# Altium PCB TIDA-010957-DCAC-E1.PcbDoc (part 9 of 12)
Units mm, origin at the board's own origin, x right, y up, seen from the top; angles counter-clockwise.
Board outline 300 x 300 mm, 4 copper layers (Top Layer, Layer 1, Layer 2, Bottom Layer), stack 1.787 mm thick; 1159 components, 619 nets, 3431 pads, 2942 vias.
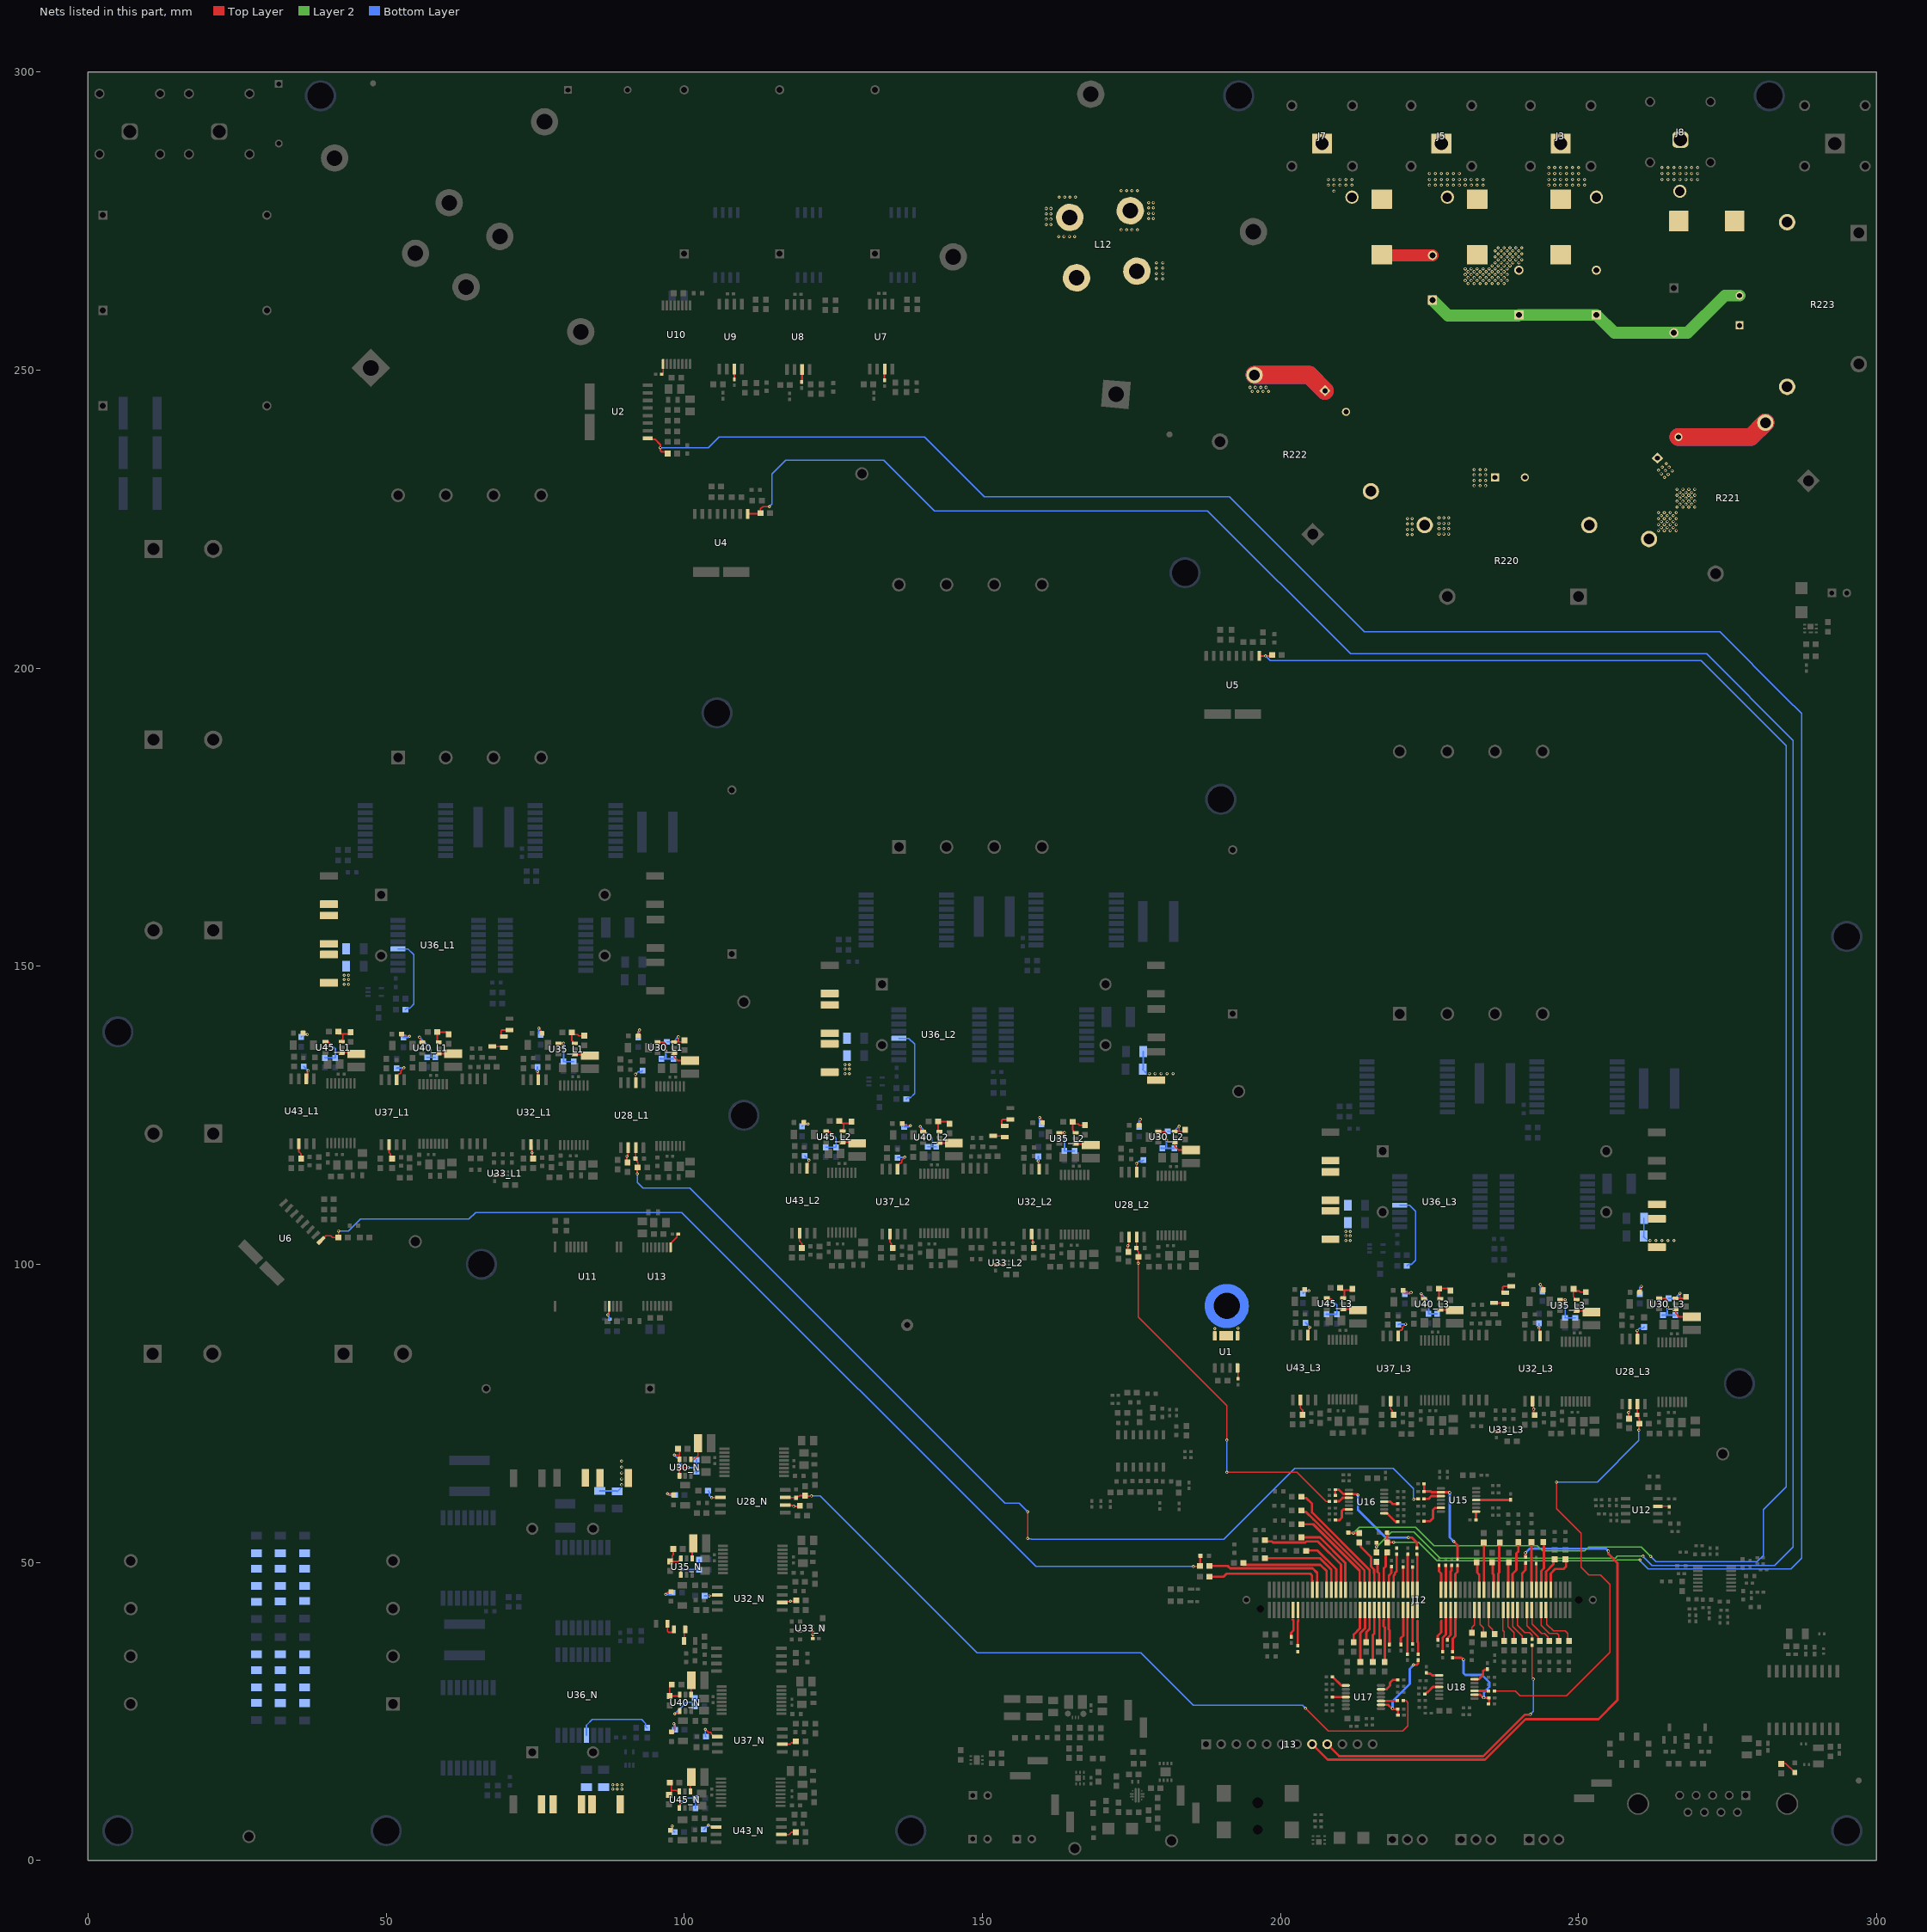
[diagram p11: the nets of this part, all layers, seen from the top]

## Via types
v1: diameter 0.508, hole 0.254, Top Layer to Bottom Layer, tented both sides, 2942 vias

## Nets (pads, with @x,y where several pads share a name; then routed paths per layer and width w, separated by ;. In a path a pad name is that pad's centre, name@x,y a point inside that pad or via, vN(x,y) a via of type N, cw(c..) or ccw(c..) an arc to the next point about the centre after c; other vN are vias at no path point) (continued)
NetD8_L2_2: D8_L2.2 R281_L2.2 R282_L2.2 | length 3.8
  Bottom Layer w0.254: R282_L2.2@176.97,135.686 176.97,132.803 R281_L2.2@176.917,132.75 176.917,132.661 R281_L2.2@177.44,132.138
  other v1: 178,132 179,132 180,132 181,132 182,132
NetD8_L3_1: D8_L3.1 D9_L3.2
NetD8_L3_2: D8_L3.2 R281_L3.2 R282_L3.2 | length 3.8
  Bottom Layer w0.254: R282_L3.2@260.97,107.686 260.97,104.803 R281_L3.2@260.917,104.75 260.917,104.661 R281_L3.2@261.44,104.138
  other v1: 262,104 263,104 264,104 265,104 266,104
NetD8_N_1: D8_N.1 D9_N.2
NetD8_N_2: D8_N.2 R281_N.2 R282_N.2 | length 3.8
  Bottom Layer w0.254: R282_N.2@85.814,61.97 88.697,61.97 R281_N.2@88.75,61.917 88.839,61.917 R281_N.2@89.362,62.44
  other v1: 89.5,63 89.5,64 89.5,65 89.5,66 89.5,67
NetD10_L1_2: D10_L1.2 R285_L1.1 | length 2.5
  Top Layer w0.3: D10_L1.2@92.3,138.2 92.462,138.362 92.462,139.262 v1(92.5,139.3)
  Bottom Layer w0.3: R285_L1.1@92.275,138.04 92.275,139.021 92.5,139.246 v1(92.5,139.3)
NetD10_L2_2: D10_L2.2 R285_L2.1 | length 2.5
  Top Layer w0.3: D10_L2.2@176.3,123.2 176.462,123.362 176.462,124.262 v1(176.5,124.3)
  Bottom Layer w0.3: R285_L2.1@176.275,123.04 176.275,124.021 176.5,124.246 v1(176.5,124.3)
NetD10_L3_2: D10_L3.2 R285_L3.1 | length 2.5
  Top Layer w0.3: D10_L3.2@260.3,95.2 260.462,95.362 260.462,96.262 v1(260.5,96.3)
  Bottom Layer w0.3: R285_L3.1@260.275,95.04 260.275,96.021 260.5,96.246 v1(260.5,96.3)
NetD10_N_2: D10_N.2 R285_N.1 | length 2.5
  Top Layer w0.3: v1(97.2,61.5) 97.238,61.462 98.138,61.462 D10_N.2@98.3,61.3
  Bottom Layer w0.3: v1(97.2,61.5) 97.254,61.5 97.479,61.275 R285_N.1@98.46,61.275
NetD11_L1_2: D11_L1.2 R296_L1.1 | length 2.6
  Top Layer w0.254: v1(75.613,139.6) 76,139.213 D11_L1.2@76,138.457
  Bottom Layer w0.254: v1(75.613,139.6) 75.613,138.774 R296_L1.1@75.93,138.457
NetD11_L2_2: D11_L2.2 R296_L2.1 | length 2.6
  Top Layer w0.254: v1(159.613,124.6) 160,124.213 D11_L2.2@160,123.457
  Bottom Layer w0.254: v1(159.613,124.6) 159.613,123.774 R296_L2.1@159.93,123.457
NetD11_L3_2: D11_L3.2 R296_L3.1 | length 2.6
  Top Layer w0.254: v1(243.613,96.6) 244,96.213 D11_L3.2@244,95.457
  Bottom Layer w0.254: v1(243.613,96.6) 243.613,95.774 R296_L3.1@243.93,95.457
NetD11_N_2: D11_N.2 R296_N.1 | length 2.6
  Top Layer w0.254: v1(96.9,44.613) 97.287,45 D11_N.2@98.043,45
  Bottom Layer w0.254: v1(96.9,44.613) 97.726,44.613 R296_N.1@98.043,44.93
NetD12_L1_2: D12_L1.2 R306_L1.1 | length 2.5
  Top Layer w0.254: D12_L1.2@52.589,138.224 52.599,138.234 53.919,138.234 v1(53.929,138.244)
  Bottom Layer w0.254: R306_L1.1@52.897,138.033 53.663,138.033 53.875,138.244 v1(53.929,138.244)
NetD12_L2_2: D12_L2.2 R306_L2.1 | length 2.5
  Top Layer w0.254: D12_L2.2@136.589,123.224 136.599,123.234 137.919,123.234 v1(137.929,123.244)
  Bottom Layer w0.254: R306_L2.1@136.897,123.033 137.663,123.033 137.875,123.244 v1(137.929,123.244)
NetD12_L3_2: D12_L3.2 R306_L3.1 | length 2.5
  Top Layer w0.254: D12_L3.2@220.589,95.224 220.599,95.234 221.919,95.234 v1(221.929,95.244)
  Bottom Layer w0.254: R306_L3.1@220.897,95.033 221.663,95.033 221.875,95.244 v1(221.929,95.244)
NetD12_N_2: D12_N.2 R306_N.1 | length 2.5
  Top Layer w0.254: v1(98.256,22.929) 98.266,22.919 98.266,21.599 D12_N.2@98.276,21.589
  Bottom Layer w0.254: v1(98.256,22.929) 98.256,22.875 98.467,22.663 R306_N.1@98.467,21.897
NetD13_L1_1: D13_L1.1 R319_L1.1 R320_L1.1
  other v1: 42.956,146.975 43.706,146.975 42.956,147.75 43.706,147.75 42.956,148.5 43.706,148.5
NetD13_L1_2: D13_L1.2 D15_L1.1
NetD13_L2_1: D13_L2.1 R319_L2.1 R320_L2.1
  other v1: 126.956,131.975 127.706,131.975 126.956,132.75 127.706,132.75 126.956,133.5 127.706,133.5
NetD13_L2_2: D13_L2.2 D15_L2.1
NetD13_L3_1: D13_L3.1 R319_L3.1 R320_L3.1
  other v1: 210.956,103.975 211.706,103.975 210.956,104.75 211.706,104.75 210.956,105.5 211.706,105.5
NetD13_L3_2: D13_L3.2 D15_L3.1
NetD13_N_1: D13_N.1 R319_N.1 R320_N.1
  other v1: 88,11.956 88.75,11.956 89.525,11.956 88,12.706 88.75,12.706 89.525,12.706
NetD13_N_2: D13_N.2 D15_N.1
NetD14_L1_1: D14_L1.1 D15_L1.2
NetD14_L2_1: D14_L2.1 D15_L2.2
NetD14_L3_1: D14_L3.1 D15_L3.2
NetD14_N_1: D14_N.1 D15_N.2
NetD16_L1_2: D16_L1.2 R323_L1.1 | length 1.9
  Top Layer w0.254: D16_L1.2@36.075,138.584 36.101,138.558 36.761,138.558 v1(36.786,138.532)
  Bottom Layer w0.254: R323_L1.1@35.768,138.109 35.768,138.134 36.116,138.482 36.668,138.482 36.718,138.532 v1(36.786,138.532)
NetD16_L2_2: D16_L2.2 R323_L2.1 | length 1.9
  Top Layer w0.254: D16_L2.2@120.075,123.584 120.101,123.558 120.761,123.558 v1(120.786,123.532)
  Bottom Layer w0.254: R323_L2.1@119.768,123.109 119.768,123.134 120.116,123.482 120.668,123.482 120.718,123.532 v1(120.786,123.532)
NetD16_L3_2: D16_L3.2 R323_L3.1 | length 1.9
  Top Layer w0.254: D16_L3.2@204.075,95.584 204.101,95.558 204.761,95.558 v1(204.786,95.532)
  Bottom Layer w0.254: R323_L3.1@203.768,95.109 203.768,95.134 204.116,95.482 204.668,95.482 204.718,95.532 v1(204.786,95.532)
NetD16_N_2: D16_N.2 R323_N.1 | length 1.9
  Top Layer w0.254: D16_N.2@97.916,5.075 97.942,5.101 97.942,5.761 v1(97.968,5.786)
  Bottom Layer w0.254: v1(97.968,5.786) 97.968,5.718 98.018,5.668 98.018,5.116 98.366,4.768 R323_N.1@98.391,4.768
NetD18_1: D18.1 R93.2 | length 2.7
  Top Layer w0.2: R93.2@284.2,16.275 284.725,16.275 D18.1@286.25,14.75
NetF1_1: F1.1 R83.2 R89.2 R220.4
NetF2_1: F2.1 R85.2 R90.2 R221.4 | length 31.4
  Top Layer w3: R85.2@266.768,238.768 278.929,238.768 R221.4@281.339,241.177
  Bottom Layer w0.5: R90.2@240,267 R90.2@240.201,266.799
  Bottom Layer w3: R85.2@266.768,238.768 278.929,238.768 R221.4@281.339,241.177
  other v1: 231.5,264.5 232.5,264.5 233.5,264.5 234.5,264.5 235.5,264.5 236.5,264.5 237.5,264.5 231,265 232,265 233,265 234,265 235,265 236,265 237,265 238,265 231.5,265.5 232.5,265.5 233.5,265.5 234.5,265.5 235.5,265.5 236.5,265.5 237.5,265.5 231,266 232,266 233,266 234,266 235,266 236,266 237,266 238,266 231.5,266.5 232.5,266.5 233.5,266.5 234.5,266.5 235.5,266.5 236.5,266.5 237.5,266.5 231,267 232,267 233,267 234,267 235,267 236,267 237,267 238,267 235.5,267.5 236.5,267.5 237.5,267.5 238.5,267.5 236,268 237,268 238,268 239,268 240,268 236.5,268.5 237.5,268.5 238.5,268.5 239.5,268.5 240.5,268.5 236,269 237,269 238,269 239,269 240,269 236.5,269.5 237.5,269.5 238.5,269.5 239.5,269.5 240.5,269.5 236,270 237,270 238,270 239,270 240,270 236.5,270.5 237.5,270.5 238.5,270.5 239.5,270.5 240.5,270.5
NetF3_1: F3.1 R87.2 R91.2 R222.4 | length 9.1
  Top Layer w0.3: F3.1@216.5,269 F3.1@216.75,269.25
  Top Layer w2: F3.1@216.75,269.25 R91.2@225.5,269.25
NetF4_1: F4.1 R89.1 R90.1 R91.1 R92.2 R94.2 R223.4 | length 56
  Top Layer w0.5: R223.4@284.8,275 R223.4@285,274.8
  Layer 2 w0.5: R91.1@225.5,261.5 R91.1@225.75,261.5
  Layer 2 w2: R91.1@225.75,261.5 228.125,259.125 R90.1@239.875,259.125 ; R90.1@240,259.25 R89.1@252.75,259.25 ; R89.1@253,259.25 256,256.25 R94.2@265.75,256.25 ; R94.2@266,256.25 268.286,256.25 274.536,262.5 R92.2@277,262.5
NetJ12_9: J12.9 R20.1 | length 6.9
  Top Layer w0.4: J12.9@245.35,45.4 245.35,48.15 246.1,48.9 247.5,48.9 247.9,49.3 247.9,50.3 R20.1@247.8,50.4
NetJ12_11: J12.11 R21.1 | length 5.6
  Top Layer w0.4: J12.11@244.55,45.4 244.55,48.45 245.788,49.688 245.788,50.2 245.988,50.4 R21.1@246,50.4
NetJ12_12: J12.12 R22.1 | length 8
  Top Layer w0.2: J12.12@244.55,42 244.7,41.85 244.7,39.6 245.8,38.5 247.8,38.5 248.2,38.1 248.2,37 R22.1@248.4,36.8
NetJ12_13: J12.13 R23.1 | length 7.9
  Top Layer w0.4: J12.13@243.75,45.4 243.75,48.55 244.2,49 R23.1@244.2,53.1
NetJ12_14: J12.14 R24.1 | length 7.2
  Top Layer w0.2: J12.14@243.75,42 243.75,39.45 245.1,38.1 246.4,38.1 246.7,37.8 R24.1@246.7,36.8
NetJ12_15: J12.15 R25.2 | length 4.4
  Top Layer w0.4: J12.15@242.95,45.4 R25.2@242.95,49.75
NetJ12_17: J12.17 R26.1 | length 8
  Top Layer w0.4: J12.17@242.15,45.4 242.125,45.425 242.125,53.325 R26.1@242.2,53.4
NetJ12_18: J12.18 R27.1 | length 6.7
  Top Layer w0.2: J12.18@242.15,42 242.207,41.943 242.207,39.693 243.8,38.1 244.3,38.1 244.917,37.483 244.917,36.983 R27.1@245.1,36.8
NetJ12_20: J12.20 R28.1 | length 6.1
  Top Layer w0.2: J12.20@241.35,42 241.35,39.35 243.217,37.483 243.217,37.083 R28.1@243.5,36.8
NetJ12_21: J12.21 R29.2 | length 4.7
  Top Layer w0.4: J12.21@240.55,45.4 240.55,48.15 241.1,48.7 R29.2@241.1,49.9
NetJ12_24: J12.24 R30.1 | length 6.4
  Top Layer w0.2: J12.24@239.75,42 239.75,39.45 241,38.2 241.8,38.2 242.2,37.8 R30.1@242.2,37.1
NetJ12_25: J12.25 R31.1 | length 8.4
  Top Layer w0.4: J12.25@238.95,45.4 238.95,48.05 239.6,48.7 239.6,51.5 239.9,51.8 R31.1@239.9,53.4
NetJ12_26: J12.26 R32.2 | length 6
  Top Layer w0.2: J12.26@238.95,42 238.95,39.25 240.525,37.675 240.525,37.175 R32.2@240.9,36.8
NetJ12_27: J12.27 R33.1 | length 4.7
  Top Layer w0.4: J12.27@238.15,45.4 238.2,45.45 R33.1@238.2,50.1
NetJ12_28: J12.28 R34.2 | length 5.6
  Top Layer w0.2: J12.28@238.15,42 238.15,39.25 239.2,38.2 R34.2@239.2,36.8
NetJ12_30: J12.30 R35.2 | length 5.3
  Top Layer w0.2: J12.30@237.35,42 237.3,41.95 237.3,38.6 237.5,38.4 R35.2@237.5,36.8
NetJ12_31: J12.31 R36.1 | length 7.9
  Top Layer w0.4: J12.31@236.55,45.4 236.55,48.15 236.699,48.299 236.699,53 R36.1@236.9,53.2
NetJ12_33: J12.33 R37.1 | length 4.7
  Top Layer w0.4: R37.1@235.7,50 235.6,49.9 235.6,48.1 235.75,47.95 J12.33@235.75,45.4
NetJ12_36: J12.36 R38.2 | length 4.5
  Top Layer w0.2: J12.36@234.95,42 234.95,39.35 235.55,38.75 235.55,38.325 R38.2@235.925,37.95
NetJ12_37: J12.37 R39.1 | length 8
  Top Layer w0.4: R39.1@234.1,53.4 234.125,53.375 234.125,45.425 J12.37@234.15,45.4
NetJ12_39: J12.39 R40.1 | length 4.9
  Top Layer w0.4: R40.1@233.1,50.1 233,50 233,48.3 233.35,47.95 J12.39@233.35,45.4
NetJ12_40: J12.40 R41.2 | length 4.4
  Top Layer w0.2: J12.40@233.35,42 233.5,41.85 233.5,39.6 234.1,39 R41.2@234.1,37.9
NetJ12_42: J12.42 R42.2 | length 4
  Top Layer w0.2: R42.2@232.1,38.2 232.1,39.1 232.55,39.55 J12.42@232.55,42
NetJ12_49: J12.49 R43.2 | length 4.1
  Top Layer w0.4: J12.49@229.35,45.4 229.35,48.05 229.7,48.4 R43.2@229.7,49.4
NetJ12_50: J12.50 R44.2 | length 5.7
  Top Layer w0.4: R44.2@228.9,35 228.9,37.2 229.35,37.65 229.35,40.45 229.4,40.5
NetJ12_51: J12.51 R45.2 | length 4.2
  Top Layer w0.4: J12.51@228.55,45.4 228.55,48.45 228.7,48.6 R45.2@228.7,49.5
NetJ12_52: J12.52 R46.2 | length 4.1
  Top Layer w0.4: R46.2@228,37 228.05,37.05 228.05,37.339 228.55,37.84 228.55,40.85 J12.52@228.6,40.9
NetJ12_53: J12.53 R47.2 | length 4.1
  Top Layer w0.4: J12.53@227.75,45.4 R47.2@227.75,49.45
NetJ12_54: J12.54 R48.2 | length 6.3
  Top Layer w0.4: R48.2@227.2,35 227.2,37.338 227.75,37.888 227.75,41.05 J12.54@227.8,41.1
NetJ12_55: J12.55 R49.2 | length 4.1
  Top Layer w0.4: R49.2@226.6,49.4 226.6,48.5 226.95,48.15 J12.55@226.95,45.4
NetJ12_56: J12.56 R50.2 | length 3.4
  Top Layer w0.4: R50.2@226.4,37 226.4,37.7 226.95,38.25 226.95,40.15 227,40.2
NetJ12_57: J12.57 R51.2 | length 6
  Top Layer w0.4: R51.2@222.9,51.4 222.9,51.35 222.95,51.3 J12.57@222.95,45.4
NetJ12_58: J12.58 R52.2 | length 5.6
  Top Layer w0.4: 223,40.2 223,36.6 223.1,36.5 R52.2@223.1,34.6
NetJ12_59: J12.59 R53.2 | length 3.8
  Top Layer w0.4: J12.59@222.15,45.4 222.175,45.425 222.175,49.175 R53.2@222.2,49.2
NetJ12_60: J12.60 R54.2 | length 4.3
  Top Layer w0.4: R54.2@222.2,36.3 222.175,36.325 222.175,40.575 222.2,40.6
NetJ12_61: J12.61 R55.2 | length 6.1
  Top Layer w0.4: J12.61@221.35,45.4 221.35,51.45 R55.2@221.4,51.5
NetJ12_62: J12.62 R56.2 | length 6
  Top Layer w0.4: R56.2@221.3,34.6 221.3,40.6
NetJ12_63: J12.63 R57.2 | length 3.8
  Top Layer w0.4: J12.63@220.55,45.4 220.575,45.425 220.575,49.175 R57.2@220.6,49.2
NetJ12_64: J12.64 R58.2 | length 4.5
  Top Layer w0.4: R58.2@220.2,36.2 220.2,37.3 220.6,37.7 220.6,40.5
NetJ12_67: J12.67 R59.2 | length 6.2
  Top Layer w0.4: J12.67@218.95,45.4 219,45.45 219,47.752 219.2,47.951 219.2,48.2 219.5,48.5 R59.2@219.5,51.4
NetJ12_69: J12.69 R60.2 | length 4.1
  Top Layer w0.4: J12.69@218.15,45.4 218.2,45.45 218.2,47.8 218.6,48.2 R60.2@218.6,49.3
NetJ12_70: J12.70 R61.2 | length 4.5
  Top Layer w0.4: 218.2,40.6 218.15,40.55 218.15,38.75 218.3,38.6 R61.2@218.3,36.2
NetJ12_71: J12.71 R62.1 | length 6.5
  Top Layer w0.4: J12.71@217.35,45.4 217.35,49.012 217.671,49.333 217.671,51.471 R62.1@217.9,51.7
NetJ12_72: J12.72 R63.2 | length 7.2
  Top Layer w0.4: 217.4,40.4 217.3,40.3 217.3,39.276 217.5,39.076 R63.2@217.5,33.3
NetJ12_73: J12.73 R64.1 | length 4.7
  Top Layer w0.4: R64.1@216.2,50 216.3,49.9 216.3,48.4 216.55,48.15 J12.73@216.55,45.4
NetJ12_74: J12.74 R65.2 | length 4.3
  Top Layer w0.4: R65.2@216.5,36.6 216.6,36.7 J12.74@216.6,40.9
NetJ12_75: J12.75 R66.1 | length 9
  Top Layer w0.4: R66.1@213.2,53.3 213.475,53.025 213.475,52.625 215.225,50.875 215.225,49.275 215.7,48.8 215.7,48.151 215.75,48.101 J12.75@215.75,45.4
NetJ12_76: J12.76 R67.2 | length 8.8
  Top Layer w0.4: R67.2@215.5,33.3 215.5,37.8 215.75,38.05 J12.76@215.75,42
NetJ12_77: J12.77 R68.1 | length 20.7
  Top Layer w0.4: R68.1@203.5,61 203.712,60.788 204.312,60.788 205.3,59.8 205.3,58.351 214.95,48.701 J12.77@214.95,45.4
NetJ12_78: J12.78 R69.2 | length 5.6
  Top Layer w0.4: R69.2@214.4,36.6 214.4,38.3 214.95,38.85 J12.78@214.95,42
NetJ12_79: J12.79 R70.1 | length 16.4
  Top Layer w0.4: R70.1@203.5,58.7 203.736,58.464 204.288,58.464 205.551,57.2 214.1,48.651 214.1,47
NetJ12_80: J12.80 R71.2 | length 7.6
  Top Layer w0.4: R71.2@213.4,33.3 213.4,38.149 214.2,38.949 214.2,40.6
NetJ12_81: J12.81 R72.1 | length 15.2
  Top Layer w0.4: R72.1@203.5,56.4 205.503,56.4 213.3,48.603 213.3,46.6 J12.81@213.4,46.5
NetJ12_82: J12.82 R84.2 | length 4.7
  Top Layer w0.4: R84.2@212.3,36.6 212.3,37.9 213.35,38.95 213.35,40.75 J12.82@213.4,40.8
NetJ12_87: J12.87 R73.1 | length 12.1
  Top Layer w0.4: R73.1@203.5,54.2 206.6,54.2 210.9,49.9 210.9,47
NetJ12_89: J12.89 R74.1 | length 18.8
  Top Layer w0.4: R74.1@197.294,53.5 198.563,53.5 198.738,53.325 204.166,53.325 204.341,53.5 206.3,53.5 210.15,49.65 J12.89@210.15,45.4
NetJ12_91: J12.91 R75.1 | length 8.5
  Top Layer w0.4: R75.1@204.3,51.9 204.4,52 206.2,52 209.35,48.85 209.35,46.85 209.4,46.8
NetJ12_93: J12.93 R76.1 | length 15.3
  Top Layer w0.4: R76.1@197.4,50.7 206.6,50.7 208.55,48.75 J12.93@208.55,45.4
NetJ12_95: J12.95 R77.1 | length 17.6
  Top Layer w0.4: R77.1@193.7,49.6 206.7,49.6 207.75,48.55 J12.95@207.75,45.4
NetJ12_99: J12.99 R78.1 | length 20.2
  Top Layer w0.4: R78.1@188.1,49.4 191.159,49.4 191.559,49 205.4,49 206.15,48.25 206.15,46.65 J12.99@206.2,46.6
NetJ12_101: J12.101 R334.1 | length 18.5
  Top Layer w0.4: R334.1@188.1,47.6 190.5,47.6 191,48.1 205,48.1 205.3,47.8 205.3,47 205.4,46.9
NetJ12_108: J12.108 R79.2 | length 4.4
  Top Layer w0.4: R79.2@202.9,36 202.9,40.076 203,40.176 203,40.4
NetJ12_110: J12.110 R80.2 | length 3.1
  Top Layer w0.4: R80.2@201.8,37.5 201.8,38.2 202.2,38.6 202.2,40.3 202.1,40.4
NetL10_L1_1: L10_L1.1 U30_L1.1 | length 3.6
  Top Layer w0.254: U30_L1.1@98.288,135.395 98.288,134.795 98.901,134.182 L10_L1.1@101,134.182
NetL10_L2_1: L10_L2.1 U30_L2.1 | length 3.6
  Top Layer w0.254: U30_L2.1@182.288,120.395 182.288,119.795 182.901,119.182 L10_L2.1@185,119.182
NetL10_L3_1: L10_L3.1 U30_L3.1 | length 3.6
  Top Layer w0.254: U30_L3.1@266.288,92.395 266.288,91.795 266.901,91.182 L10_L3.1@269,91.182
NetL10_N_1: L10_N.1 U30_N.1 | length 3.6
  Top Layer w0.254: U30_N.1@101.105,67.288 101.705,67.288 102.318,67.901 L10_N.1@102.318,70
NetL12_2: L12.2 R83.1 R220.3
  other v1: 221.3,222.4 222.1,222.4 226.6,222.5 227.4,222.5 228.2,222.5 221.3,223.3 222.1,223.3 226.6,223.4 227.4,223.4 228.2,223.4 221.3,224.2 222.1,224.2 226.6,224.3 227.4,224.3 228.2,224.3 221.3,225.1 222.1,225.1 226.6,225.2 227.4,225.2 228.2,225.2 232.5,230.6 233.5,230.6 234.4,230.6 232.5,231.5 233.5,231.5 234.4,231.5 232.5,232.4 233.5,232.4 234.4,232.4 232.5,233.3 233.5,233.3 234.4,233.3 179.2,265.3 180.3,265.3 179.2,266.2 180.3,266.2 179.2,267.1 180.3,267.1 179.2,268 180.3,268
NetL12_4: L12.4 R85.1 R221.3 | length 0.7
  Bottom Layer w0.5: R221.3@261.823,221.661 262,221.484 R221.3@262,221
  other v1: 263.391,223.085 264.391,223.085 265.391,223.085 266.391,223.085 263.891,223.585 264.891,223.585 265.891,223.585 263.391,224.085 264.391,224.085 265.391,224.085 266.391,224.085 263.891,224.585 264.891,224.585 265.891,224.585 263.391,225.085 264.391,225.085 265.391,225.085 266.391,225.085 263.891,225.585 264.891,225.585 265.891,225.585 263.391,226.085 264.391,226.085 265.391,226.085 266.391,226.085 266.5,227 267.5,227 268.5,227 269.5,227 267,227.5 268,227.5 269,227.5 266.5,228 267.5,228 268.5,228 269.5,228 267,228.5 268,228.5 269,228.5 266.5,229 267.5,229 268.5,229 269.5,229 267,229.5 268,229.5 269,229.5 266.5,230 267.5,230 268.5,230 269.5,230 264.4,232 265.038,232.519 263.9,232.6 265.7,233.1 264.538,233.119 263.4,233.2 265.2,233.7 264.038,233.719 264.7,234.3 173.3,273.5 174.2,273.5 175.1,273.5 176,273.5 177.9,275.4 178.7,275.4 177.9,276.3 178.7,276.3 177.9,277.2 178.7,277.2 177.9,278.1 178.7,278.1 173.3,280.1 174.2,280.1 175.1,280.1 176,280.1
NetL12_6: L12.6 R87.1 R222.3 | length 25.8
  Top Layer w3: R222.3@195.661,249.177 204.823,249.177 R87.1@207.464,246.536
  Bottom Layer w3: R222.3@195.661,249.177 204.823,249.177 R87.1@207.464,246.536
  other v1: 195.3,246.4 196.2,246.4 197.1,246.4 198,246.4 194.9,247.1 195.8,247.1 196.7,247.1 197.6,247.1 162.8,272.4 163.7,272.4 164.6,272.4 165.5,272.4 160.7,274.4 161.5,274.4 160.7,275.3 161.5,275.3 160.7,276.2 161.5,276.2 160.7,277.1 161.5,277.1 162.9,279 163.8,279 164.7,279 165.6,279
NetL12_8: L12.8 R92.1 R223.3
NetL12_L1_1: L12_L1.1 U35_L1.1 | length 2.6
  Top Layer w0.254: U35_L1.1@81.65,135.166 84.005,135.166 L12_L1.1@84.173,134.998
NetL12_L2_1: L12_L2.1 U35_L2.1 | length 2.6
  Top Layer w0.254: U35_L2.1@165.65,120.166 168.005,120.166 L12_L2.1@168.173,119.998
NetL12_L3_1: L12_L3.1 U35_L3.1 | length 2.6
  Top Layer w0.254: U35_L3.1@249.65,92.166 252.005,92.166 L12_L3.1@252.173,91.998
NetL12_N_1: L12_N.1 U35_N.1 | length 2.6
  Top Layer w0.254: U35_N.1@101.334,50.65 101.334,53.005 L12_N.1@101.502,53.173
NetL14_L1_1: L14_L1.1 U40_L1.1 | length 2.4
  Top Layer w0.254: U40_L1.1@58.833,135.333 61.209,135.333 L14_L1.1@61.225,135.316
NetL14_L2_1: L14_L2.1 U40_L2.1 | length 2.4
  Top Layer w0.254: U40_L2.1@142.833,120.333 145.209,120.333 L14_L2.1@145.225,120.316
NetL14_L3_1: L14_L3.1 U40_L3.1 | length 2.4
  Top Layer w0.254: U40_L3.1@226.833,92.333 229.209,92.333 L14_L3.1@229.225,92.316
NetL14_N_1: L14_N.1 U40_N.1 | length 2.4
  Top Layer w0.254: U40_N.1@101.167,27.833 101.167,30.209 L14_N.1@101.184,30.225
NetL16_L1_1: L16_L1.1 U45_L1.1 | length 2.6
  Top Layer w0.254: U45_L1.1@42.507,135.5 44.785,135.5 L16_L1.1@44.994,135.291
NetL16_L2_1: L16_L2.1 U45_L2.1 | length 2.6
  Top Layer w0.254: U45_L2.1@126.507,120.5 128.785,120.5 L16_L2.1@128.994,120.291
NetL16_L3_1: L16_L3.1 U45_L3.1 | length 2.6
  Top Layer w0.254: U45_L3.1@210.507,92.5 212.785,92.5 L16_L3.1@212.994,92.291
NetL16_N_1: L16_N.1 U45_N.1 | length 2.6
  Top Layer w0.254: U45_N.1@101,11.507 101,13.785 L16_N.1@101.209,13.994
NetMP12_1: MP12.1 U1.5 U1.6 U1.7
  other v1: 189,89.2 192.9,89.3
NetR1_1: R1.1 R2.1 R3.1 R4.2 R5.2 R6.2
NetR4_1: R4.1 R5.1 R6.1 R7.2 R8.2 R9.2
NetR10_1: R10.1 R11.1 R12.1 R13.2 R14.2 R15.2
NetR13_1: R13.1 R14.1 R15.1 R16.2 R17.2 R18.2
NetR19_2: R19.2 U1.4 | length 1.8
  Top Layer w0.2: U1.4@192.805,82.6 192.853,82.553 192.853,80.848 R19.2@192.9,80.8
NetR130_1: R130.1 U7.7 | length 1.7
  Top Layer w0.3: R130.1@133.6,248.3 133.6,249.7 U7.7@133.8,249.9
NetR132_1: R132.1 U8.7 | length 2.2
  Top Layer w0.3: R132.1@119.6,248 119.77,248.17 U8.7@119.77,250.1
NetR134_1: R134.1 U9.7 | length 1.4
  Top Layer w0.3: R134.1@108.405,248.445 108.405,249.705 U9.7@108.5,249.8
NetR136_2: R136.2 U10.1 | length 1.8
  Top Layer w0.2: R136.2@96.2,249.3 96.25,249.3 96.45,249.5 U10.1@96.45,251
NetR138_1: R138.1 U11.3 | length 1.7
  Top Layer w0.3: v1(87.2,91.5) 87.2,91.584 87.354,91.738 87.354,92.179 87.44,92.265 U11.3@87.465,92.265
  Bottom Layer w0.3: v1(87.2,91.5) 87.2,91.416 87.379,91.237 87.379,90.868 87.448,90.8 R138.1@87.5,90.8
NetR143_2: R143.2 U13.1 | length 2.8
  Top Layer w0.2: U13.1@97.713,102.854 97.713,103.474 98.8,104.561 98.8,104.95 98.95,105.1 R143.2@99,105.1
NetR165_1: R165.1 U15.3 | length 2.8
  Top Layer w0.4: R165.1@224.1,60.65 224.85,60.65 225.3,61.1 U15.3@226.7,61.1
NetR166_1: R166.1 U15.6 | length 4.6
  Top Layer w0.4: R166.1@224.1,56.9 225.1,56.9 225.6,57.4 225.6,58.8 225.942,59.142 226.912,59.142 U15.6@226.921,59.152
NetR167_1: R167.1 U15.8 | length 1.4
  Top Layer w0.4: R167.1@232.8,57.1 232.811,57.111 232.811,58.491 U15.8@232.821,58.502
NetR168_1: R168.1 U15.11 | length 5.9
  Top Layer w0.4: U15.11@232.821,60.452 238.55,60.452 238.6,60.502 R168.1@238.6,60.6
NetR176_1: R176.1 U16.3 | length 2.7
  Top Layer w0.4: R176.1@209.1,60.2 209.15,60.25 209.85,60.25 210.425,60.825 U16.3@211.498,60.825
NetR177_1: R177.1 U17.3 | length 2.8
  Top Layer w0.4: U17.3@216.866,26.752 219.552,26.752 R177.1@219.6,26.8
NetR178_1: R178.1 U16.6 | length 3.6
  Top Layer w0.4: R178.1@209.3,57.1 209.9,57.1 210.3,57.5 210.3,58.631 210.534,58.865 211.488,58.865 U16.6@211.498,58.875
NetR179_1: R179.1 U17.6 | length 3.8
  Top Layer w0.4: U17.6@216.866,28.702 216.876,28.712 217.812,28.712 218.4,29.3 218.4,29.8 218.9,30.3 R179.1@219.7,30.3
NetR180_1: R180.1 U16.8 | length 2.9
  Top Layer w0.4: U16.8@217.398,58.225 217.875,58.225 219.3,56.8 R180.1@219.7,56.8
NetR181_1: R181.1 U17.8 | length 2.7
  Top Layer w0.4: R181.1@208.8,30.75 210.188,29.362 210.957,29.362 U17.8@210.966,29.352
NetR182_1: R182.1 U16.11 | length 2.5
  Top Layer w0.4: U16.11@217.398,60.175 217.408,60.165 218.435,60.165 218.8,59.8 R182.1@219.7,59.8
NetR183_1: R183.1 U17.11 | length 2.3
  Top Layer w0.4: R183.1@208.7,27.4 R183.1@208.7,27.4 210.965,27.401 U17.11@210.966,27.402
NetR195_1: R195.1 U18.3 | length 2.5
  Top Layer w0.4: U18.3@232.55,28.45 232.56,28.44 234.96,28.44 R195.1@235,28.4
NetR196_1: R196.1 U18.6 | length 3.3
  Top Layer w0.4: U18.6@232.55,30.4 232.56,30.41 233.268,30.41 234,31.141 234,31.766 234.234,32 R196.1@234.8,32
NetR197_1: R197.1 U18.8 | length 2.3
  Top Layer w0.4: R197.1@224.5,31.4 224.55,31.35 225.15,31.35 225.45,31.05 U18.8@226.65,31.05
NetR198_1: R198.1 U18.11 | length 2.9
  Top Layer w0.4: R198.1@224.266,27.916 224.6,28.25 224.716,28.25 225.556,29.09 226.64,29.09 U18.11@226.65,29.1
NetR278_L1_2: R278_L1.2 U28_L1.2 | length 2.6
  Top Layer w0.254: R278_L1.2@90.48,117.092 90.394,117.178 v1(90.394,118.13) 90.394,118.199 90.575,118.379 90.575,119.51 U28_L1.2@90.615,119.55
NetR278_L2_2: R278_L2.2 U28_L2.2 | length 2.6
  Top Layer w0.254: R278_L2.2@174.48,102.092 174.394,102.178 v1(174.394,103.13) 174.394,103.199 174.575,103.379 174.575,104.51 U28_L2.2@174.615,104.55
NetR278_L3_2: R278_L3.2 U28_L3.2 | length 2.6
  Top Layer w0.254: R278_L3.2@258.48,74.092 258.394,74.178 v1(258.394,75.13) 258.394,75.199 258.575,75.379 258.575,76.51 U28_L3.2@258.615,76.55
NetR278_N_2: R278_N.2 U28_N.2 | length 2.6
  Top Layer w0.254: U28_N.2@116.95,59.615 116.99,59.575 118.121,59.575 118.301,59.394 v1(118.37,59.394) 119.322,59.394 R278_N.2@119.408,59.48
NetR279_L1_1: R279_L1.1 U28_L1.6 | length 2.9
  Top Layer w0.254: v1(91.838,131.871) 91.862,131.848 91.862,130.473 U28_L1.6@91.885,130.45
  Bottom Layer w0.254: v1(91.838,131.871) 92.253,132.286 92.813,132.286 R279_L1.1@93,132.473
NetR279_L2_1: R279_L2.1 U28_L2.6 | length 2.9
  Top Layer w0.254: v1(175.838,116.871) 175.862,116.848 175.862,115.473 U28_L2.6@175.885,115.45
  Bottom Layer w0.254: v1(175.838,116.871) 176.253,117.286 176.813,117.286 R279_L2.1@177,117.473
NetR279_L3_1: R279_L3.1 U28_L3.6 | length 2.9
  Top Layer w0.254: v1(259.838,88.871) 259.862,88.848 259.862,87.473 U28_L3.6@259.885,87.45
  Bottom Layer w0.254: v1(259.838,88.871) 260.253,89.286 260.813,89.286 R279_L3.1@261,89.473
NetR279_N_1: R279_N.1 U28_N.6 | length 2.9
  Top Layer w0.254: v1(104.629,60.838) 104.652,60.862 106.027,60.862 U28_N.6@106.05,60.885
  Bottom Layer w0.254: R279_N.1@104.027,62 104.214,61.813 104.214,61.253 v1(104.629,60.838)
NetR286_L1_1: R286_L1.1 R288_L1.2 U30_L1.4 | length 6.1
  Top Layer w0.3: U30_L1.4@95.538,137.295 96.505,137.295 96.9,136.9 v1(96.9,135.8)
  Bottom Layer w0.3: R288_L1.2@96,134.5 96.031,134.469 R288_L1.2@96.172,134.469 R286_L1.1@98.204,134.469 ; 96.9,134.5 v1(96.9,135.8)
NetR286_L2_1: R286_L2.1 R288_L2.2 U30_L2.4 | length 6.1
  Top Layer w0.3: U30_L2.4@179.538,122.295 180.505,122.295 180.9,121.9 v1(180.9,120.8)
  Bottom Layer w0.3: R288_L2.2@180,119.5 180.031,119.469 R288_L2.2@180.172,119.469 R286_L2.1@182.204,119.469 ; 180.9,119.5 v1(180.9,120.8)
NetR286_L3_1: R286_L3.1 R288_L3.2 U30_L3.4 | length 6.1
  Top Layer w0.3: U30_L3.4@263.538,94.295 264.505,94.295 264.9,93.9 v1(264.9,92.8)
  Bottom Layer w0.3: R288_L3.2@264,91.5 264.031,91.469 R288_L3.2@264.172,91.469 R286_L3.1@266.204,91.469 ; 264.9,91.5 v1(264.9,92.8)
NetR286_N_1: R286_N.1 R288_N.2 U30_N.4 | length 6.1
  Top Layer w0.3: U30_N.4@99.205,64.538 99.205,65.505 99.6,65.9 v1(100.7,65.9)
  Bottom Layer w0.3: v1(100.7,65.9) 102,65.9 ; R288_N.2@102,65 102.031,65.031 R288_N.2@102.031,65.172 R286_N.1@102.031,67.204
NetR289_L1_1: R289_L1.1 R290_L1.2 U30_L1.3 | length 5
  Top Layer w0.254: U30_L1.3@98.288,137.295 99.013,137.295 ; v1(99.013,138.145) 99.013,137.295 ; R290_L1.2@100.047,137.54 99.802,137.295 99.013,137.295
  Bottom Layer w0.254: R289_L1.1@97.113,137.295 98.163,137.295 v1(99.013,138.145)
NetR289_L2_1: R289_L2.1 R290_L2.2 U30_L2.3 | length 5
  Top Layer w0.254: U30_L2.3@182.288,122.295 183.013,122.295 ; v1(183.013,123.145) 183.013,122.295 ; R290_L2.2@184.047,122.54 183.802,122.295 183.013,122.295
  Bottom Layer w0.254: R289_L2.1@181.113,122.295 182.163,122.295 v1(183.013,123.145)
NetR289_L3_1: R289_L3.1 R290_L3.2 U30_L3.3 | length 5
  Top Layer w0.254: U30_L3.3@266.288,94.295 267.013,94.295 ; v1(267.013,95.145) 267.013,94.295 ; R290_L3.2@268.047,94.54 267.802,94.295 267.013,94.295
  Bottom Layer w0.254: R289_L3.1@265.113,94.295 266.163,94.295 v1(267.013,95.145)
NetR289_N_1: R289_N.1 R290_N.2 U30_N.3 | length 5
  Top Layer w0.254: v1(98.355,68.013) 99.205,68.013 ; R290_N.2@98.96,69.047 99.205,68.802 99.205,68.013 ; U30_N.3@99.205,67.288 99.205,68.013
  Bottom Layer w0.254: v1(98.355,68.013) 99.205,67.163 R289_N.1@99.205,66.113
NetR291_L1_2: R291_L1.2 U32_L1.2 | length 2.5
  Top Layer w0.254: U32_L1.2@74.275,120.05 74.424,119.901 74.424,118.74 v1(74.473,118.692) 74.473,117.898 R291_L1.2@74.66,117.711
NetR291_L2_2: R291_L2.2 U32_L2.2 | length 2.5
  Top Layer w0.254: U32_L2.2@158.275,105.05 158.424,104.901 158.424,103.74 v1(158.473,103.692) 158.473,102.898 R291_L2.2@158.66,102.711
NetR291_L3_2: R291_L3.2 U32_L3.2 | length 2.5
  Top Layer w0.254: U32_L3.2@242.275,77.05 242.424,76.901 242.424,75.74 v1(242.473,75.692) 242.473,74.898 R291_L3.2@242.66,74.711
NetR291_N_2: R291_N.2 U32_N.2 | length 2.5
  Top Layer w0.254: U32_N.2@116.45,43.275 116.599,43.424 117.76,43.424 v1(117.808,43.473) 118.602,43.473 R291_N.2@118.789,43.66
NetR292_L1_1: R292_L1.1 U32_L1.6 | length 2.2
  Top Layer w0.254: v1(75.385,132.332) 75.434,132.284 75.434,131.061 U32_L1.6@75.545,130.95
  Bottom Layer w0.254: v1(75.385,132.332) R292_L1.1@75.385,133.082
NetR292_L2_1: R292_L2.1 U32_L2.6 | length 2.2
  Top Layer w0.254: v1(159.385,117.332) 159.434,117.284 159.434,116.061 U32_L2.6@159.545,115.95
  Bottom Layer w0.254: v1(159.385,117.332) R292_L2.1@159.385,118.082
NetR292_L3_1: R292_L3.1 U32_L3.6 | length 2.2
  Top Layer w0.254: v1(243.385,89.332) 243.434,89.284 243.434,88.061 U32_L3.6@243.545,87.95
  Bottom Layer w0.254: v1(243.385,89.332) R292_L3.1@243.385,90.082
NetR292_N_1: R292_N.1 U32_N.6 | length 2.2
  Top Layer w0.254: v1(104.168,44.385) 104.216,44.434 105.439,44.434 U32_N.6@105.55,44.545
  Bottom Layer w0.254: R292_N.1@103.418,44.385 v1(104.168,44.385)
NetR293_L1_2: R293_L1.2 U33_L1.4 | length 1.3
  Top Layer w0.254: R293_L1.2@68.2,114.934 v1(68.881,114.934) 68.898,114.951 69.44,114.951 U33_L1.4@69.456,114.967
NetR293_L2_2: R293_L2.2 U33_L2.4 | length 1.3
  Top Layer w0.254: R293_L2.2@152.2,99.934 v1(152.881,99.934) 152.898,99.951 153.44,99.951 U33_L2.4@153.456,99.967
NetR293_L3_2: R293_L3.2 U33_L3.4 | length 1.3
  Top Layer w0.254: R293_L3.2@236.2,71.934 v1(236.881,71.934) 236.898,71.951 237.44,71.951 U33_L3.4@237.456,71.967
NetR293_N_2: R293_N.2 U33_N.4 | length 1.3
  Top Layer w0.254: U33_N.4@121.533,38.456 121.549,38.44 121.549,37.898 v1(121.566,37.881) R293_N.2@121.566,37.2
NetR297_L1_1: R297_L1.1 R299_L1.2 U35_L1.4 | length 5.7
  Top Layer w0.254: U35_L1.4@78.9,137.066 78.903,137.062 79.772,137.062 v1(79.775,137.059)
  Bottom Layer w0.254: v1(79.775,137.059) 79.775,134.046 R299_L1.2@79.736,134.007 R297_L1.1@81.456,134.007
NetR297_L2_1: R297_L2.1 R299_L2.2 U35_L2.4 | length 5.7
  Top Layer w0.254: U35_L2.4@162.9,122.066 162.903,122.062 163.772,122.062 v1(163.775,122.059)
  Bottom Layer w0.254: v1(163.775,122.059) 163.775,119.046 R299_L2.2@163.736,119.007 R297_L2.1@165.456,119.007
NetR297_L3_1: R297_L3.1 R299_L3.2 U35_L3.4 | length 5.7
  Top Layer w0.254: U35_L3.4@246.9,94.066 246.903,94.062 247.772,94.062 v1(247.775,94.059)
  Bottom Layer w0.254: v1(247.775,94.059) 247.775,91.046 R299_L3.2@247.736,91.007 R297_L3.1@249.456,91.007
NetR297_N_1: R297_N.1 R299_N.2 U35_N.4 | length 5.7
  Top Layer w0.254: U35_N.4@99.434,47.9 99.438,47.903 99.438,48.772 v1(99.441,48.775)
  Bottom Layer w0.254: v1(99.441,48.775) 102.454,48.775 R299_N.2@102.493,48.736 R297_N.1@102.493,50.456
NetR300_L1_1: R300_L1.1 R301_L1.2 U35_L1.3 | length 4.5
  Top Layer w0.254: U35_L1.3@81.65,137.066 81.45,137.066 81.277,137.239 81.277,137.439 81.144,137.572 R300_L1.1@81.144,138.875 81.492,138.527 82.106,138.527 82.299,138.334 R301_L1.2@83.244,138.334
NetR300_L2_1: R300_L2.1 R301_L2.2 U35_L2.3 | length 4.5
  Top Layer w0.254: U35_L2.3@165.65,122.066 165.45,122.066 165.277,122.239 165.277,122.439 165.144,122.572 R300_L2.1@165.144,123.875 165.492,123.527 166.106,123.527 166.299,123.334 R301_L2.2@167.244,123.334
NetR300_L3_1: R300_L3.1 R301_L3.2 U35_L3.3 | length 4.5
  Top Layer w0.254: U35_L3.3@249.65,94.066 249.45,94.066 249.277,94.239 249.277,94.439 249.144,94.572 R300_L3.1@249.144,95.875 249.492,95.527 250.106,95.527 250.299,95.334 R301_L3.2@251.244,95.334
NetR300_N_1: R300_N.1 R301_N.2 U35_N.3 | length 4.5
  Top Layer w0.254: R301_N.2@98.166,52.244 98.166,51.299 97.973,51.106 97.973,50.492 R300_N.1@97.625,50.144 98.928,50.144 99.061,50.277 99.261,50.277 99.434,50.45 U35_N.3@99.434,50.65
NetR302_L1_2: R302_L1.2 U37_L1.2 | length 2.5
  Top Layer w0.254: U37_L1.2@50.494,120.05 50.494,118.744 50.733,118.505 50.733,118.022 R302_L1.2@51,117.755
NetR302_L2_2: R302_L2.2 U37_L2.2 | length 2.5
  Top Layer w0.254: U37_L2.2@134.494,105.05 134.494,103.744 134.733,103.505 134.733,103.022 R302_L2.2@135,102.755
NetR302_L3_2: R302_L3.2 U37_L3.2 | length 2.5
  Top Layer w0.254: U37_L3.2@218.494,77.05 218.494,75.744 218.733,75.505 218.733,75.022 R302_L3.2@219,74.755
NetR302_N_2: R302_N.2 U37_N.2 | length 2.5
  Top Layer w0.254: U37_N.2@116.45,19.494 117.756,19.494 117.995,19.733 118.478,19.733 R302_N.2@118.745,20
NetR303_L1_1: R303_L1.1 U37_L1.6 | length 3.9
  Top Layer w0.254: U37_L1.6@51.764,130.95 51.764,131.55 52.181,131.968 52.34,131.968 52.489,132.116 52.489,132.46 v1(52.986,132.956)
  Bottom Layer w0.254: R303_L1.1@51.764,132.866 51.854,132.956 v1(52.986,132.956)
NetR303_L2_1: R303_L2.1 U37_L2.6 | length 3.9
  Top Layer w0.254: U37_L2.6@135.764,115.95 135.764,116.55 136.181,116.968 136.34,116.968 136.489,117.116 136.489,117.46 v1(136.986,117.956)
  Bottom Layer w0.254: R303_L2.1@135.764,117.866 135.854,117.956 v1(136.986,117.956)
NetR303_L3_1: R303_L3.1 U37_L3.6 | length 3.9
  Top Layer w0.254: U37_L3.6@219.764,87.95 219.764,88.55 220.181,88.968 220.34,88.968 220.489,89.116 220.489,89.46 v1(220.986,89.956)
  Bottom Layer w0.254: R303_L3.1@219.764,89.866 219.854,89.956 v1(220.986,89.956)
NetR303_N_1: R303_N.1 U37_N.6 | length 3.9
  Top Layer w0.254: v1(103.544,21.986) 104.04,21.489 104.384,21.489 104.532,21.34 104.532,21.181 104.95,20.764 U37_N.6@105.55,20.764
  Bottom Layer w0.254: v1(103.544,21.986) 103.544,20.854 R303_N.1@103.634,20.764
NetR304_L1_2: R304_L1.2 U36_L1.12 | length 13.1
  Bottom Layer w0.254: U36_L1.12@52,152.9 53.675,152.9 54.654,151.921 54.654,143.657 53.972,142.975 53.472,142.975 R304_L1.2@53.222,142.725
NetR304_L2_2: R304_L2.2 U36_L2.12 | length 13.1
  Bottom Layer w0.254: U36_L2.12@136,137.9 137.675,137.9 138.654,136.921 138.654,128.657 137.972,127.975 137.472,127.975 R304_L2.2@137.222,127.725
NetR304_L3_2: R304_L3.2 U36_L3.12 | length 13.1
  Bottom Layer w0.254: U36_L3.12@220,109.9 221.675,109.9 222.654,108.921 222.654,100.657 221.972,99.975 221.472,99.975 R304_L3.2@221.222,99.725
NetR304_N_2: R304_N.2 U36_N.12 | length 13.1
  Bottom Layer w0.254: U36_N.12@83.6,21 83.6,22.675 84.579,23.654 92.843,23.654 93.525,22.972 93.525,22.472 R304_N.2@93.775,22.222
NetR307_L1_1: R307_L1.1 R309_L1.2 U40_L1.4 | length 6.7
  Top Layer w0.254: v1(55.61,138.083) 55.61,138.014 55.71,137.914 55.71,137.406 55.883,137.233 U40_L1.4@56.083,137.233
  Bottom Layer w0.254: v1(55.61,138.083) 57.533,136.16 57.533,134.707 ; R309_L1.2@56.86,134.707 57.533,134.707 ; R307_L1.1@58.258,134.707 57.533,134.707
NetR307_L2_1: R307_L2.1 R309_L2.2 U40_L2.4 | length 6.7
  Top Layer w0.254: v1(139.61,123.083) 139.61,123.014 139.71,122.914 139.71,122.406 139.883,122.233 U40_L2.4@140.083,122.233
  Bottom Layer w0.254: v1(139.61,123.083) 141.533,121.16 141.533,119.707 ; R309_L2.2@140.86,119.707 141.533,119.707 ; R307_L2.1@142.258,119.707 141.533,119.707
NetR307_L3_1: R307_L3.1 R309_L3.2 U40_L3.4 | length 6.5
  Top Layer w0.254: v1(223.61,95.083) 223.61,95.014 223.71,94.914 223.71,94.406 223.883,94.233 U40_L3.4@224.083,94.233
  Bottom Layer w0.254: v1(223.61,95.083) 224.86,93.833 R309_L3.2@224.86,91.707 R307_L3.1@226.258,91.707
NetR307_N_1: R307_N.1 R309_N.2 U40_N.4 | length 6.7
  Top Layer w0.254: v1(98.417,24.61) 98.486,24.61 98.586,24.71 99.094,24.71 99.267,24.883 U40_N.4@99.267,25.083
  Bottom Layer w0.254: v1(98.417,24.61) 100.34,26.533 101.793,26.533 ; R309_N.2@101.793,25.86 101.793,26.533 ; R307_N.1@101.793,27.258 101.793,26.533
NetR310_L1_1: R310_L1.1 R311_L1.2 U40_L1.3 | length 3.9
  Top Layer w0.254: U40_L1.3@58.833,137.233 58.756,137.233 58.583,137.406 R310_L1.1@58.583,138.942 60.152,138.942 60.5,138.594 R311_L1.2@60.5,138.584
NetR310_L2_1: R310_L2.1 R311_L2.2 U40_L2.3 | length 3.9
  Top Layer w0.254: U40_L2.3@142.833,122.233 142.756,122.233 142.583,122.406 R310_L2.1@142.583,123.942 144.152,123.942 144.5,123.594 R311_L2.2@144.5,123.584
NetR310_L3_1: R310_L3.1 R311_L3.2 U40_L3.3 | length 3.9
  Top Layer w0.254: U40_L3.3@226.833,94.233 226.756,94.233 226.583,94.406 R310_L3.1@226.583,95.942 228.152,95.942 228.5,95.594 R311_L3.2@228.5,95.584
NetR310_N_1: R310_N.1 R311_N.2 U40_N.3 | length 3.9
  Top Layer w0.254: R311_N.2@97.916,29.5 97.906,29.5 97.558,29.152 R310_N.1@97.558,27.583 99.094,27.583 99.267,27.756 U40_N.3@99.267,27.833
NetR312_L1_2: R312_L1.2 R313_L1.1 | length 1.7
  Top Layer w0.25: R312_L1.2@67.829,136.54 67.869,136.5 R313_L1.1@69.5,136.5
NetR312_L2_2: R312_L2.2 R313_L2.1 | length 1.7
  Top Layer w0.25: R312_L2.2@151.829,121.54 151.869,121.5 R313_L2.1@153.5,121.5
NetR312_L3_2: R312_L3.2 R313_L3.1 | length 1.7
  Top Layer w0.25: R312_L3.2@235.829,93.54 235.869,93.5 R313_L3.1@237.5,93.5
NetR312_N_2: R312_N.2 R313_N.1 | length 1.7
  Top Layer w0.25: R312_N.2@99.96,36.829 100,36.869 R313_N.1@100,38.5
NetR313_L1_2: R313_L1.2 R314_L1.1 | length 1.9
  Top Layer w0.254: R313_L1.2@69.339,138.532 69.275,138.597 69.275,139.151 69.423,139.3 R314_L1.1@70.5,139.3
NetR313_L2_2: R313_L2.2 R314_L2.1 | length 1.9
  Top Layer w0.254: R313_L2.2@153.339,123.532 153.275,123.597 153.275,124.151 153.423,124.3 R314_L2.1@154.5,124.3
NetR313_L3_2: R313_L3.2 R314_L3.1 | length 1.9
  Top Layer w0.254: R313_L3.2@237.339,95.532 237.275,95.597 237.275,96.151 237.423,96.3 R314_L3.1@238.5,96.3
NetR313_N_2: R313_N.2 R314_N.1 | length 1.9
  Top Layer w0.254: R314_N.1@97.2,39.5 97.2,38.423 97.349,38.275 97.903,38.275 R313_N.2@97.968,38.339
NetR316_L1_2: R316_L1.2 U43_L1.2 | length 2.6
  Top Layer w0.254: U43_L1.2@35.343,120.226 35.343,118.907 35.725,118.525 R316_L1.2@35.725,117.755
NetR316_L2_2: R316_L2.2 U43_L2.2 | length 2.6
  Top Layer w0.254: U43_L2.2@119.343,105.226 119.343,103.907 119.725,103.525 R316_L2.2@119.725,102.755
NetR316_L3_2: R316_L3.2 U43_L3.2 | length 2.6
  Top Layer w0.254: U43_L3.2@203.343,77.226 203.343,75.907 203.725,75.525 R316_L3.2@203.725,74.755
NetR316_N_2: R316_N.2 U43_N.2 | length 2.6
  Top Layer w0.254: U43_N.2@116.274,4.343 117.593,4.343 117.975,4.725 R316_N.2@118.745,4.725
NetR317_L1_1: R317_L1.1 U43_L1.6 | length 2.5
  Top Layer w0.254: U43_L1.6@36.613,131.126 36.786,131.299 36.786,132.24 36.925,132.379 v1(36.925,132.448)
  Bottom Layer w0.254: R317_L1.1@36.2,133.198 36.548,132.85 36.548,132.825 v1(36.925,132.448)
NetR317_L2_1: R317_L2.1 U43_L2.6 | length 2.5
  Top Layer w0.254: U43_L2.6@120.613,116.126 120.786,116.299 120.786,117.24 120.925,117.379 v1(120.925,117.448)
  Bottom Layer w0.254: R317_L2.1@120.2,118.198 120.548,117.85 120.548,117.825 v1(120.925,117.448)
NetR317_L3_1: R317_L3.1 U43_L3.6 | length 2.5
  Top Layer w0.254: U43_L3.6@204.613,88.126 204.786,88.299 204.786,89.24 204.925,89.379 v1(204.925,89.448)
  Bottom Layer w0.254: R317_L3.1@204.2,90.198 204.548,89.85 204.548,89.825 v1(204.925,89.448)
NetR317_N_1: R317_N.1 U43_N.6 | length 2.5
  Top Layer w0.254: v1(104.052,5.925) 104.121,5.925 104.26,5.786 105.201,5.786 U43_N.6@105.374,5.613
  Bottom Layer w0.254: R317_N.1@103.302,5.2 103.65,5.548 103.675,5.548 v1(104.052,5.925)
NetR324_L1_1: R324_L1.1 R326_L1.2 U45_L1.4 | length 5.8
  Top Layer w0.254: U45_L1.4@39.413,137.334 40.324,137.334 v1(40.751,136.908)
  Bottom Layer w0.254: R326_L1.2@39.726,134.623 R324_L1.1@41.476,134.623 41.476,136.183 v1(40.751,136.908)
NetR324_L2_1: R324_L2.1 R326_L2.2 U45_L2.4 | length 5.5
  Top Layer w0.254: U45_L2.4@123.801,122.334 123.939,122.195 124.463,122.195 v1(124.751,121.908)
  Bottom Layer w0.254: R326_L2.2@123.726,119.623 R324_L2.1@125.476,119.623 125.476,121.183 v1(124.751,121.908)
NetR324_L3_1: R324_L3.1 R326_L3.2 U45_L3.4 | length 5.7
  Top Layer w0.254: U45_L3.4@207.585,94.4 207.79,94.195 208.463,94.195 v1(208.751,93.908)
  Bottom Layer w0.254: R326_L3.2@207.726,91.623 R324_L3.1@209.476,91.623 209.476,93.183 v1(208.751,93.908)
NetR324_N_1: R324_N.1 R326_N.2 U45_N.4 | length 5.6
  Top Layer w0.254: U45_N.4@99.1,8.733 99.305,8.938 99.305,9.463 v1(99.592,9.751)
  Bottom Layer w0.254: v1(99.592,9.751) 100.317,10.476 R324_N.1@101.877,10.476 R326_N.2@101.877,8.726
NetR327_L1_1: R327_L1.1 R328_L1.2 U45_L1.3 | length 3.3
  Top Layer w0.254: R327_L1.1@42.003,138.659 42.753,138.659 43.892,138.659 R328_L1.2@44.044,138.508 ; U45_L1.3@42.551,137.581 42.754,137.784 42.754,138.659
NetR327_L2_1: R327_L2.1 R328_L2.2 U45_L2.3 | length 3.4
  Top Layer w0.254: R327_L2.1@126.003,124.059 126.351,123.711 126.473,123.711 126.525,123.659 126.754,123.659 ; U45_L2.3@126.551,122.581 126.754,122.784 126.754,123.659 ; R328_L2.2@128.044,123.658 127.894,123.658 127.892,123.659 126.753,123.659
NetR327_L3_1: R327_L3.1 R328_L3.2 U45_L3.3 | length 3.3
  Top Layer w0.254: R327_L3.1@210.003,95.659 210.753,95.659 211.892,95.659 R328_L3.2@212.044,95.508 ; U45_L3.3@210.551,94.581 210.754,94.784 210.754,95.659
NetR327_N_1: R327_N.1 R328_N.2 U45_N.3 | length 3.3
  Top Layer w0.254: R327_N.1@97.841,11.003 97.841,11.753 97.841,12.892 R328_N.2@97.992,13.044 ; 97.841,11.754 98.716,11.754 U45_N.3@98.919,11.551
NetR332_2: R332.2 U12.7 | length 1.9
  Top Layer w0.2: U12.7@263.3,59.41 265.09,59.41 R332.2@265.2,59.3
OC_L1: C33.1 R62.2 R99.1 U2.3 | length 431.8
  Top Layer w0.3: U2.3@93.875,238.555 94.025,238.405 95.095,238.405 96,237.5 v1(96,236.988) 96,236.476 96.176,236.3 97,236.3 R99.1@97.2,236.1
  Top Layer w0.4: R62.2@217.9,53.4 C33.1@217.9,55 ; R62.2@218,53.4 218.04,53.36 218.96,53.36 v1(219,53.4)
  Layer 2 w0.2: v1(219,53.4) 223.2,53.4 226.305,50.295 256.334,50.295 256.439,50.4 v1(260.3,50.4)
  Bottom Layer w0.2: v1(96,236.988) 104.028,236.988 105.84,238.8 140.3,238.8 150.351,228.749 191.451,228.749 214.1,206.1 273.7,206.1 284.7,195.1 287.4,192.4 287.4,50.7 285.6,48.9 261.7,48.9 260.3,50.3 v1(260.3,50.4)
OC_L2: C39.1 R64.2 R109.1 U4.3 | length 413.8
  Top Layer w0.2: R109.1@112.8,226 112.8,226.7 113.2,227.1 v1(114.3,227.1)
  Top Layer w0.3: U4.3@110.6,226 110.725,225.875 112.675,225.875 R109.1@112.8,226
  Top Layer w0.4: R64.2@216.1,51.7 v1(216.1,52.6) C39.1@216.1,53.3
  Layer 2 w0.2: v1(216.1,52.6) 218.6,55.1 222.4,55.1 226.805,50.695 256.168,50.695 256.509,51.036 v1(260.829,51.036)
  Bottom Layer w0.2: v1(114.3,227.1) 114.3,227.146 114.705,227.551 114.705,228.195 114.7,228.2 114.7,232.6 117,234.9 133.5,234.9 142,226.4 187.8,226.4 211.794,202.406 271.477,202.406 286,187.883 286,52.6 282.861,49.461 262.339,49.461 260.829,50.971 v1(260.829,51.036)
OC_L3: C45.1 R66.2 R117.1 U5.3 | length 307.6
  Top Layer w0.3: U5.3@196.5,202.2 196.5,202.135 196.595,202.04 v1(197.518,202.04) 198.44,202.04 R117.1@198.6,202.2
  Top Layer w0.4: C45.1@211.4,55 211.46,54.94 212.16,54.94 v1(212.2,54.9) 213,54.9 R66.2@213.1,55
  Layer 2 w0.2: v1(212.2,54.9) 213.2,55.9 222.7,55.9 225.8,52.8 243.1,52.8 244,51.9 251,51.9 251.7,52.6 260.5,52.6 v1(262.1,51)
  Bottom Layer w0.2: v1(197.518,202.04) 198.296,201.263 270.537,201.263 284.8,187 284.8,62.679 280.993,58.871 280.993,51.15 279.943,50.1 263,50.1 v1(262.1,51)
OC_N: C52.1 R78.2 R123.1 U6.3 | length 176.6
  Top Layer w0.2: U6.3@39.09,104.01 39.88,104.8 40.7,104.8 41,104.5 R123.1@42,104.5 v1(42,105.6) ; v1(185.4,49.3) 186.4,49.3 R78.2@186.55,49.45
  Top Layer w0.4: R78.2@186.55,49.45 186.55,51.05 C52.1@186.6,51.1
  Bottom Layer w0.2: v1(42,105.6) 43.7,105.6 45.7,107.6 63.9,107.6 65,108.7 99.6,108.7 159,49.3 v1(185.4,49.3)
PCC_L1: F1.2 J3.1 TP2.1
  other v1: 245,281 246,281 247,281 248,281 249,281 250,281 251,281 245,282 246,282 247,282 248,282 249,282 250,282 251,282 245,283 246,283 247,283 248,283 249,283 250,283 245,284 246,284 247,284 248,284 249,284 250,284
PCC_L2: F2.2 J5.1 TP3.1
  other v1: 225,281 226,281 227,281 228,281 229,281 230,281 231,281 232.013,281.006 233,281 234,281 225,282 226,282 227,282 228,282 229,282 230,282 231,282 232,282 233,282 234,282 225,283 226,283 227,283 228,283 229,283 230,283
PCC_L3: F3.2 J7.1 TP4.1
  other v1: 209,280 208,281 209,281 210,281 211,281 212,281 208,282 209,282 210,282 211,282 212,282
PCC_N: F4.2 J8.1 TP7.1
  other v1: 264,282 265,282 266,282 267,282 268,282 269,282 270,282 264,283 265,283 266,283 267,283 268,283 269,283 270,283 264,284 265,284 266,284 267,284 268,284 269,284 270,284
PWM_S1_GaN_A: J13.8 R29.1 | length 97
  Top Layer w0.4: J13.8@205.31,19.5 207.91,16.9 234.297,16.9 241.097,23.7 253.349,23.7 256.547,26.899 256.547,49.901 255.014,51.434 255.014,51.886 v1(255,51.9) ; R29.1@241.1,50.9 v1@241.1,51.4
  Bottom Layer w0.4: v1(241.1,51.6) 241.795,52.295 242.598,52.295 242.608,52.305 243.192,52.305 243.197,52.3 254.6,52.3 v1(255,51.9)
PWM_S1_GaN_B: R59.1
PWM_S1_GaN_BUF_L1: C191_L1.2 R165.2 R284_L1.2 U28_L1.3 | length 172.6
  Top Layer w0.2: v1(157.6,54) v1(157.6,58.5) ; v1(222.352,60.569) 222.399,60.617 223.067,60.617 R165.2@223.1,60.65
  Top Layer w0.254: U28_L1.3@91.885,119.55 91.862,119.527 91.862,117.762 C191_L1.2@91.838,117.738 92.061,117.515 92.061,117.25 92.2,117.111 R284_L1.2@92.2,116.255 92.125,116.18 v1(92.125,115.18)
  Bottom Layer w0.2: v1(92.125,115.18) 92.125,113.725 93.057,112.793 100.907,112.793 153.8,59.9 156.2,59.9 v1(157.6,58.5) ; v1(157.6,54) 157.678,53.922 158.183,53.922 158.205,53.9 190.5,53.9 202.4,65.8 218.9,65.8 222.3,62.4 222.3,60.62 v1(222.352,60.569)
PWM_S1_GaN_BUF_L2: C191_L2.2 R176.2 R284_L2.2 U28_L2.3 | length 65
  Top Layer w0.2: v1(176.125,100.18) 176.125,91.175 191,76.3 v1(191,70.5) ; v1(191,65.1) 202.8,65.1 207.7,60.2 R176.2@208.2,60.2
  Top Layer w0.254: U28_L2.3@175.885,104.55 175.862,104.527 175.862,102.762 C191_L2.2@175.838,102.738 176.061,102.515 176.061,102.25 176.2,102.111 R284_L2.2@176.2,101.255 176.125,101.18 v1(176.125,100.18)
  Bottom Layer w0.2: v1(191,65.1) v1(191,70.5)
PWM_S1_GaN_BUF_L3: C191_L3.2 R195.2 R284_L3.2 U28_L3.3 | length 79.2
  Top Layer w0.2: R195.2@235.9,28.4 239.4,28.4 240.2,27.6 248,27.6 255.3,34.9 255.3,46.3 253.7,47.9 251.7,47.9 250.4,49.2 250.4,54.9 246.3,59 v1(246.3,63.446)
  Top Layer w0.254: U28_L3.3@259.885,76.55 259.862,76.527 259.862,74.762 C191_L3.2@259.838,74.738 260.061,74.515 260.061,74.25 260.2,74.111 R284_L3.2@260.2,73.255 260.125,73.18 v1(260.125,72.18)
  Bottom Layer w0.2: v1(246.3,63.446) 253.146,63.446 260.125,70.425 260.125,70.725 260.125,70.825 v1(260.125,72.18)
PWM_S1_GaN_BUF_N: C191_N.2 R177.2 R284_N.2 U28_N.3 | length 126.2
  Top Layer w0.2: v1(204.2,25.5) 208,21.7 220.5,21.7 221.4,22.6 221.4,26.5 221.1,26.8 R177.2@220.6,26.8
  Top Layer w0.254: U28_N.3@116.95,60.885 116.973,60.862 118.738,60.862 C191_N.2@118.762,60.838 118.985,61.061 119.25,61.061 119.389,61.2 R284_N.2@120.245,61.2 120.32,61.125 v1(121.32,61.125)
  Top Layer w0.4: R177.2@220.6,26.8 R177.2@220.65,26.75
  Bottom Layer w0.2: v1(121.32,61.125) 122.775,61.125 149.1,34.8 176.6,34.8 185.4,26 203.7,26 v1(204.2,25.5)
PWM_S1_GaN_L1: C109.1 R43.1 R170.2 U15.2 | length 17.4
  Top Layer w0.4: R170.2@224.1,63.15 C109.1@224.1,61.9 225.2,61.9 225.348,61.752 228.288,61.752 228.343,61.697 v1(228.4,61.697) ; v1@229.1,53.5 229.7,52.9 R43.1@229.7,50.5
  Bottom Layer w0.4: v1(228.4,61.697) 228.405,61.692 228.405,54.178 v1(229.088,53.496)
PWM_S1_GaN_L2: C116.1 R51.1 R185.2 U16.2 | length 20.5
  Top Layer w0.4: C116.1@209.2,61.2 R185.2@209.2,62.2 209.8,62.2 210.515,61.485 U16.2@211.488,61.485 ; U16.2@211.7,61.5 211.75,61.45 212.793,61.45 212.943,61.3 v1(213,61.3) ; v1(221.475,54.163) 221.478,54.16 222.04,54.16 222.9,53.3 R51.1@222.9,52.4
  Bottom Layer w0.4: v1(213,61.3) 213,58.846 217.683,54.163 v1(221.475,54.163)
PWM_S1_GaN_L3: C127.1 R44.1 R200.2 U18.2 | length 15.8
  Top Layer w0.4: R44.1@228.9,34 230.343,34 230.643,33.7 v1(230.7,33.7) ; U18.2@232.55,27.8 232.56,27.79 233.51,27.79 234.05,27.25 R200.2@234.95,27.25 ; C127.1@234.893,26.25 234.943,26.25 234.993,26.3 234.993,26.527 235,26.534 R200.2@235,27.2
  Bottom Layer w0.4: v1(230.7,33.7) 230.7,31.4 231,31.1 233.8,31.1 235.034,29.866 235.034,29.091 234.14,28.197 234.14,27.34 v1(234.1,27.3)
PWM_S1_GaN_N: C121.1 R52.1 R190.2 U17.2 | length 14.1
  Top Layer w0.4: U17.2@217,26.1 217.007,26.093 218.107,26.093 218.8,25.4 C121.1@219.6,25.4 ; R190.2@219.708,24.361 R190.2@219.716,24.369 C121.1@219.716,25.384 ; v1(222.3,32.8) 222.833,32.8 223.067,33.034 223.067,33.567 R52.1@223.1,33.6
  Bottom Layer w0.4: v1(218.8,25.5) 218.8,26.7 221.694,29.594 221.694,32.137 222.3,32.743 v1(222.3,32.8)
PWM_S2_GaN_A: J13.9 R30.2 | length 49.7
  Top Layer w0.2: R30.2@242.2,36.1 242.2,30.711 242.4,30.511 v1(242.4,30.4)
  Top Layer w0.4: J13.9@207.85,19.5 209.85,17.5 234.049,17.5 241.008,24.46 241.86,24.46 v1(241.9,24.5)
  Bottom Layer w0.2: v1(241.9,24.5) 241.9,24.512 242.4,25.012 v1(242.4,30.4)
PWM_S2_GaN_B: R79.1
